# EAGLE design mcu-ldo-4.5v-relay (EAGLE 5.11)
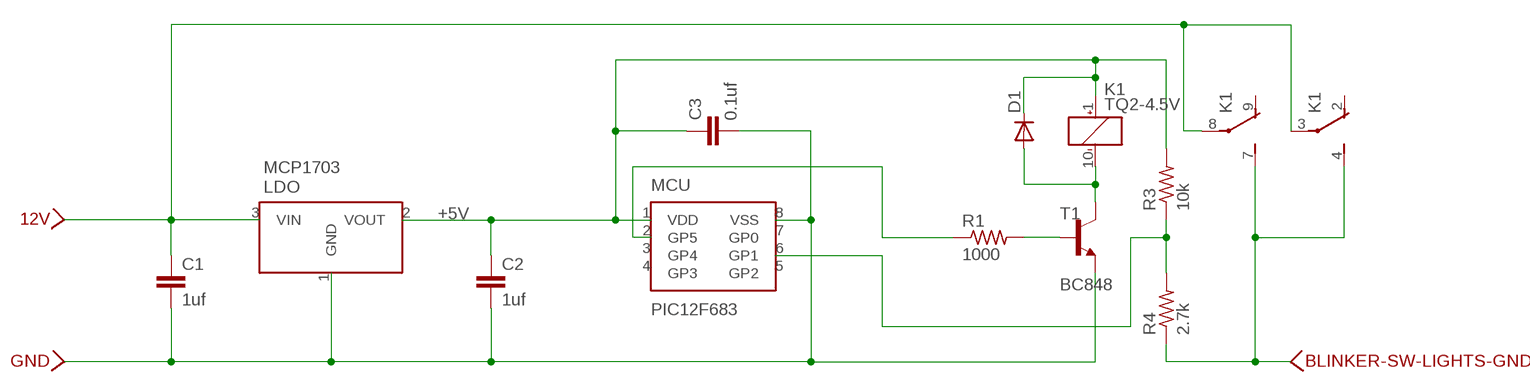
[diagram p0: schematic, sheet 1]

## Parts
12V  WIREPAD-SMD-SMALL-NAMED  [WIREPAD-SMD-SMALL]
BLINKER-SW-LIGHTS-GND  WIREPAD-SMD-SMALL-NAMED  [WIREPAD-SMD-SMALL]
C1  1uf  C-EUC0805  [C0805]
C2  1uf  C-EUC0805  [C0805]
C3  0.1uf  C-EUC0805  [C0805]
D1  DIODE-SOD323-R  [SOD323-R]
GND  WIREPAD-SMD-SMALL-NAMED  [WIREPAD-SMD-SMALL]
K1  TQ2-4.5V  [TQ2]
LDO  MCP1703  [SOT23-3]
MCU  PIC12F683  [DIL8-3]
R1  1000  R-US_R0805  [R0805]
R3  10k  R-US_R0805  [R0805]
R4  2.7k  R-US_R1206  [R1206]
T1  BC848  [SOT23]

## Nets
+5V: C2.1 C3.1 D1.C K1.1(_:+) LDO.2(VOUT) MCU.1(VDD) R3.2
GND: C1.2 C2.2 C3.2 GND.1 LDO.1(GND) MCU.8(VSS) T1.2(E)
N$1: 12V.1 C1.1 K1.3(1:P) K1.8(2:P) LDO.3(VIN)
N$2: R1.2 T1.1(B)
N$3: MCU.2(GP5) R1.1
N$4: D1.A K1.10(_:-) T1.3(C)
N$5: MCU.6(GP1) R3.1 R4.2
N$8: BLINKER-SW-LIGHTS-GND.1 K1.4(1:S) K1.7(2:S) R4.1
Unconnected: K1.2(1:O) K1.9(2:O) MCU.3(GP4) MCU.4(GP3) MCU.5(GP2) MCU.7(GP0)

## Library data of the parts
12V BLINKER-SW-LIGHTS-GND GND = trl:WIREPAD-SMD-SMALL-NAMED
C1-C3 = rcl:C-EU: CAPACITOR, European symbol
D1 = diode:DIODE-: DIODE
K1 = relay:TQ2?*: LOW PROFILE 2 FORM C RELAY NAiS Source: http://www.mew-europe.com/.. en_ds_61020_0001.pdf Source: http://www.mew-europe.com/.. en_ds_61020_0004.pdf; MF: AROMAT/ MATSUSHITA; MPN: TQ2-4.5V; OC_FARNELL: 1163566; OC_NEWARK: 64K3199
LDO = trl:MCP1703
MCU = trl:PIC12F683
R1 R3 R4 = rcl:R-US_: RESISTOR, American symbol
T1 = transistor:BC848: NPN TRANSISTOR

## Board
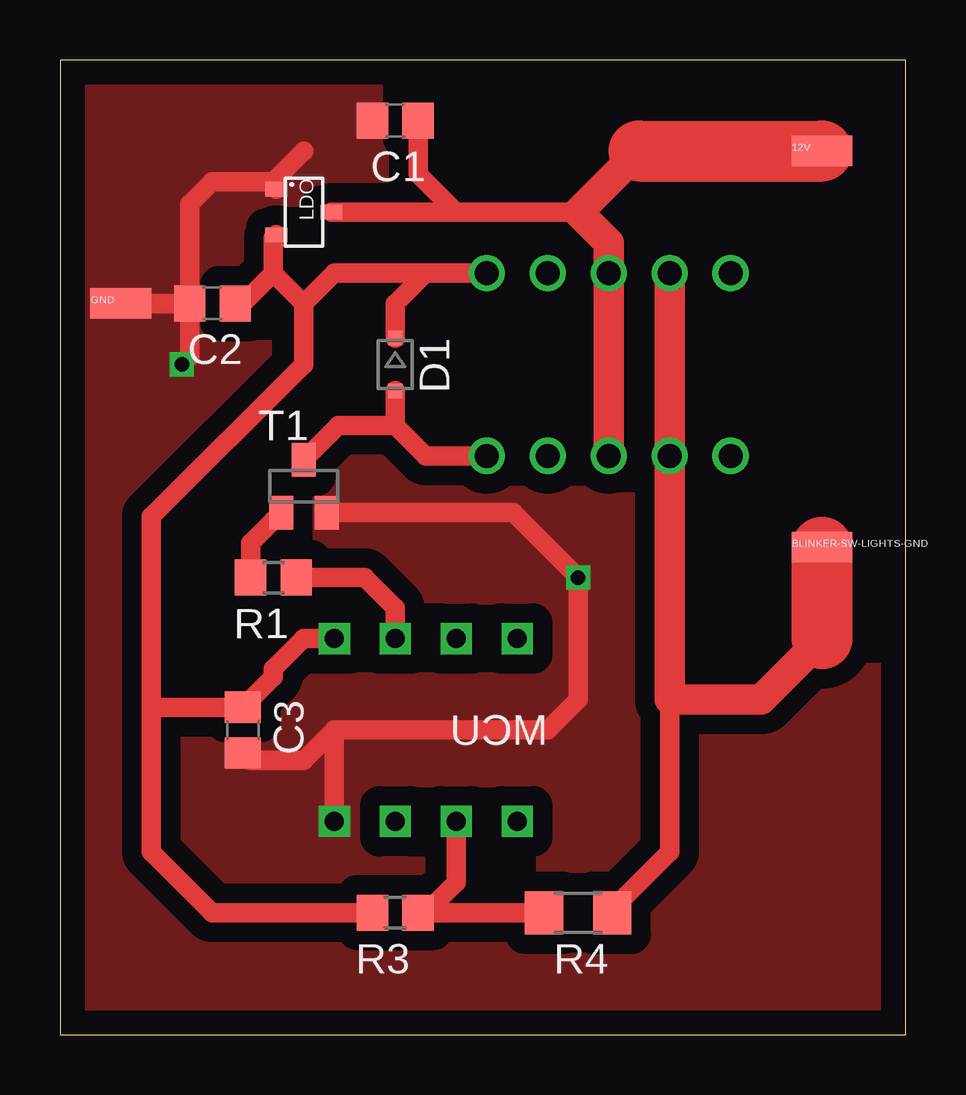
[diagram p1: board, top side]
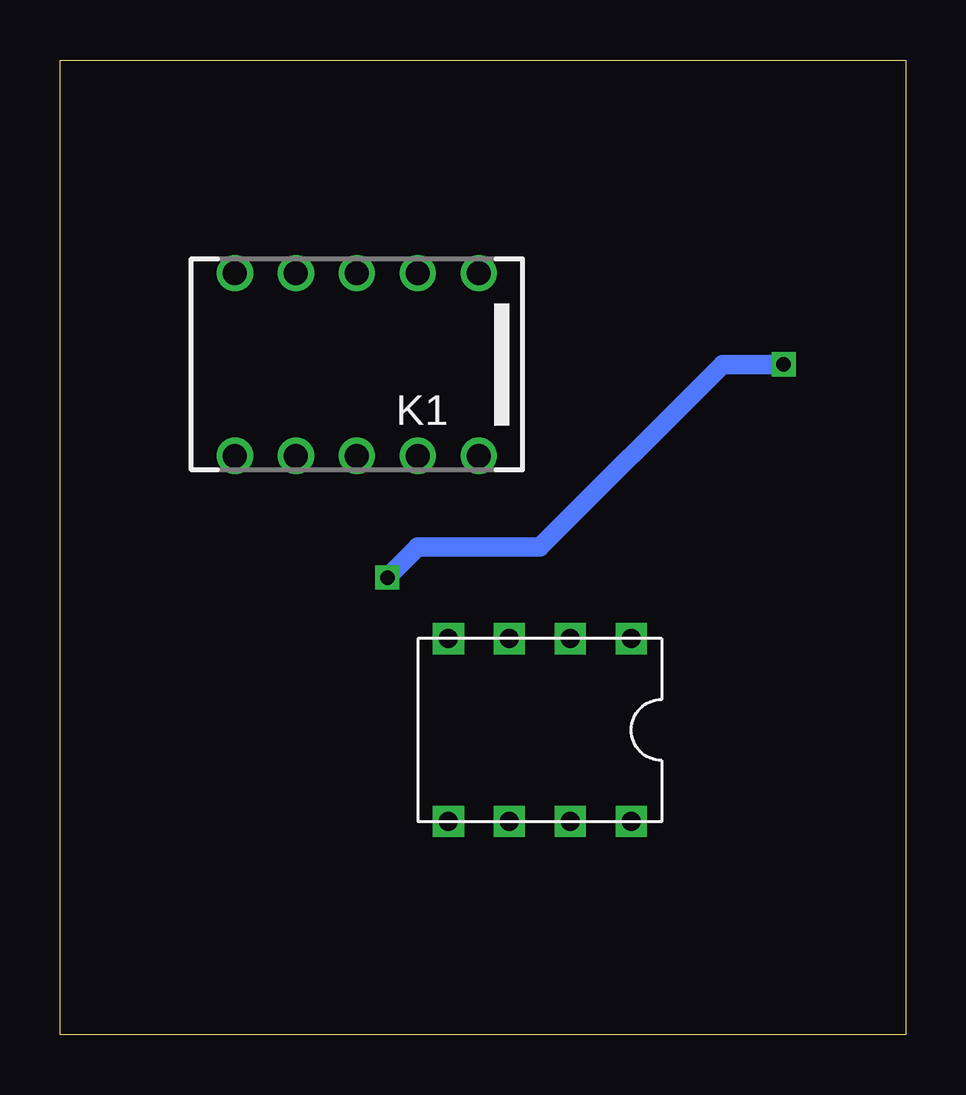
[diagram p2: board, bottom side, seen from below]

Size 35.23 x 40.63 mm. Coordinates in mm from the lower left corner, seen from the top.
Outline: 0,0 35.23,0 35.23,40.63 0,40.63 0,0
Copper layers (1*16): Top 0.035mm / dielectric 1.5mm / Bottom 0.035mm
Design rules "default": minimum track width 10mil, minimum drill 0.6mm, track to track 8mil, track to pad 8mil, pad to pad 8mil, via to via 8mil, smd to smd 8mil, copper to edge 40mil, drill to drill 8mil, minimum pad ring 10mil, minimum via ring 8mil, stop-mask expansion 4mil, vias tented up to drill 0mil, thermal gap 10mil

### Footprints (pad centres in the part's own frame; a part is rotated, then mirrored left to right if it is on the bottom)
WIREPAD-SMD-SMALL = smd 2.54 x 1.27: 1 0,0
C0805 = smd 1.3 x 1.5: 1 -0.95,0; 2 0.95,0
SOD323-R = smd 0.6 x 0.6: A 1.1,0; C -1.1,0
TQ2 = drill 1 round: 1 -5.08,-3.81; 2 -2.54,-3.81; 3 0,-3.81; 4 2.54,-3.81; 5 5.08,-3.81; 6 5.08,3.81; 7 2.54,3.81; 8 0,3.81; 9 -2.54,3.81; 10 -5.08,3.81
SOT23-3 = smd 0.6 x 0.9: 1 -0.95,-1.15; 2 0.95,-1.15; 3 0,1.15
DIL8-3 = drill 0.8 square: 1 -3.81,3.81; 2 -3.81,1.27; 3 -3.81,-1.27; 4 -3.81,-3.81; 5 3.81,-3.81; 6 3.81,-1.27; 7 3.81,1.27; 8 3.81,3.81
R0805 = smd 1.3 x 1.5: 1 -0.95,0; 2 0.95,0
R1206 = smd 1.6 x 1.803: 1 -1.422,0; 2 1.422,0
SOT23 = smd 1 x 1.4: 1 -0.95,-1.1; 2 0.95,-1.1; 3 0,1.1

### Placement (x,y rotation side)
12V  31.75,36.83 0 top
BLINKER-SW-LIGHTS-GND  31.75,20.32 0 top
C1  13.97,38.1 180 top
C2  6.35,30.48 180 top
C3  7.62,12.7 270 top
D1  13.97,27.94 270 top
GND  2.54,30.48 0 top
K1  22.86,27.94 180 bottom
LDO  10.16,34.29 270 top
MCU  15.24,12.7 270 bottom
R1  8.89,19.05 180 top
R3  13.97,5.08 180 top
R4  21.59,5.08 180 top
T1  10.16,22.86 0 top

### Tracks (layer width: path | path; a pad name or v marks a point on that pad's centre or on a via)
+5V
  Top 0.813: D1.C 13.97,30.48 15.24,31.75 | 15.24,31.75 K1.1 | R3.2 6.35,5.08 3.81,7.62 3.81,13.65 | 3.81,13.65 C3.1 8.89,14.92 8.89,15.24 10.16,16.51 MCU.1 | 3.81,13.65 3.81,21.59 10.16,27.94 10.16,30.48 | C2.1 7.62,30.48 8.89,31.75 | 8.89,31.75 8.89,33.22 LDO.2 | 10.16,30.48 11.43,31.75 15.24,31.75 | 10.16,30.48 8.89,31.75
GND  (via drill 0.6)
  Top 0.813: 11.43,12.7 20.32,12.7 21.59,13.97 v21.59,19.05 18.88,21.76 T1.2 | v5.08,27.94 5.4,28.26 C2.2 | 11.43,12.7 10.16,11.43 7.94,11.43 C3.2 | MCU.8 11.43,12.7 | C2.2 GND.1 | C2.2 5.4,34.61 6.35,35.56 8.69,35.56 LDO.1 8.89,35.36 8.89,35.56 10.16,36.83
  Bottom 0.813: v5.08,27.94 7.62,27.94 15.24,20.32 20.32,20.32 v21.59,19.05
  pour Top (isolate 0.813, no thermals): 34.29,40.64 0,40.64 0,0 34.29,0
N$1
  Top 0.813: LDO.3 16.51,34.29 | 16.51,34.29 21.59,34.29 | C1.1 14.92,35.88 16.51,34.29
  Top 1.27: K1.8 K1.3 22.86,33.02 21.59,34.29 24.13,36.83
  Top 2.54: 24.13,36.83 12V.1
N$2
  Top 0.813: 8.89,21.44 T1.1 7.94,20.49 R1.2
N$3
  Top 0.813: R1.1 12.7,19.05 13.97,17.78 MCU.2
N$4
  Top 0.813: K1.10 15.24,24.13 13.97,25.4 | 13.97,25.4 11.6,25.4 T1.3 | 13.97,25.4 D1.A
N$5
  Top 0.813: R4.2 R3.1 15.24,5.08 16.51,6.35 MCU.6
N$8
  Top 0.813: R4.1 23.01,5.23 25.4,7.62 25.4,13.97
  Top 1.27: 31.75,16.51 29.21,13.97 25.4,13.97 K1.7 K1.4
  Top 2.54: 31.75,16.51 BLINKER-SW-LIGHTS-GND.1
